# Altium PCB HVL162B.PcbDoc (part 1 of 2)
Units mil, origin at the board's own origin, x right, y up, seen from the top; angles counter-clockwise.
Board outline 4000 x 2700 mil, 2 copper layers (Top Layer, Bottom Layer), stack 62 mil thick; 115 components, 45 nets, 233 pads, 126 vias.
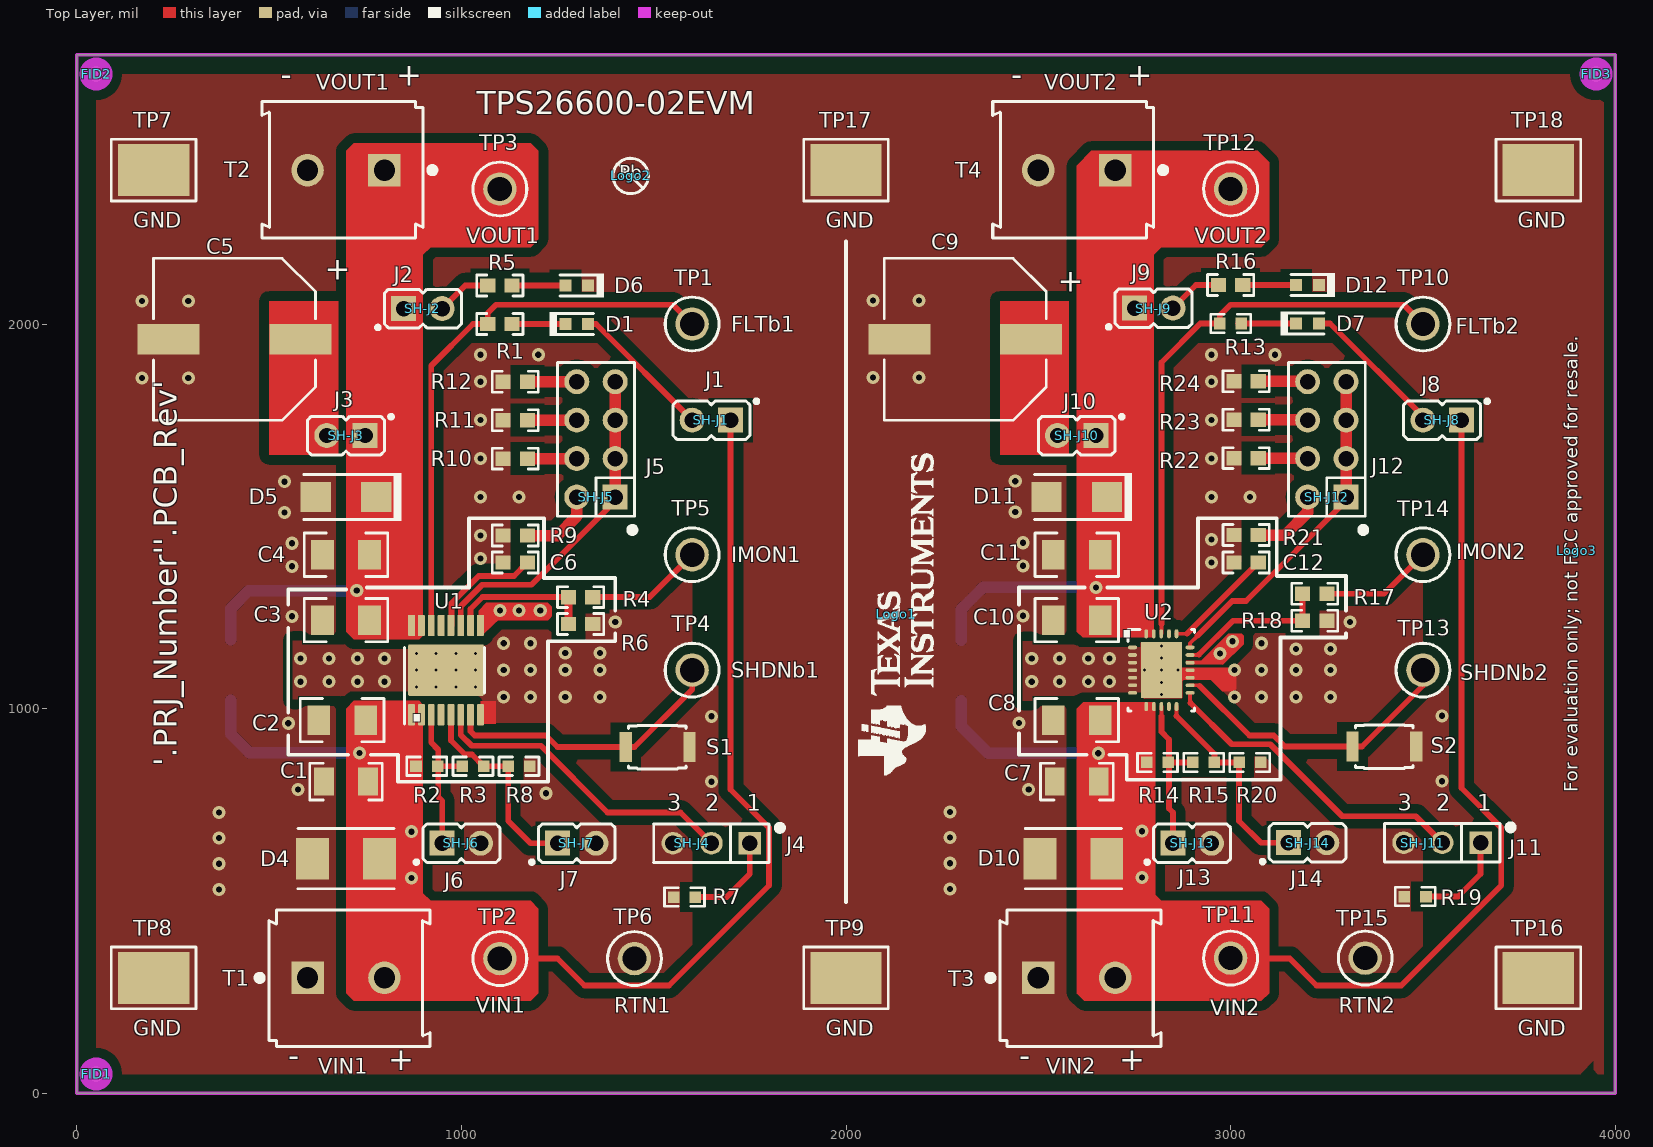
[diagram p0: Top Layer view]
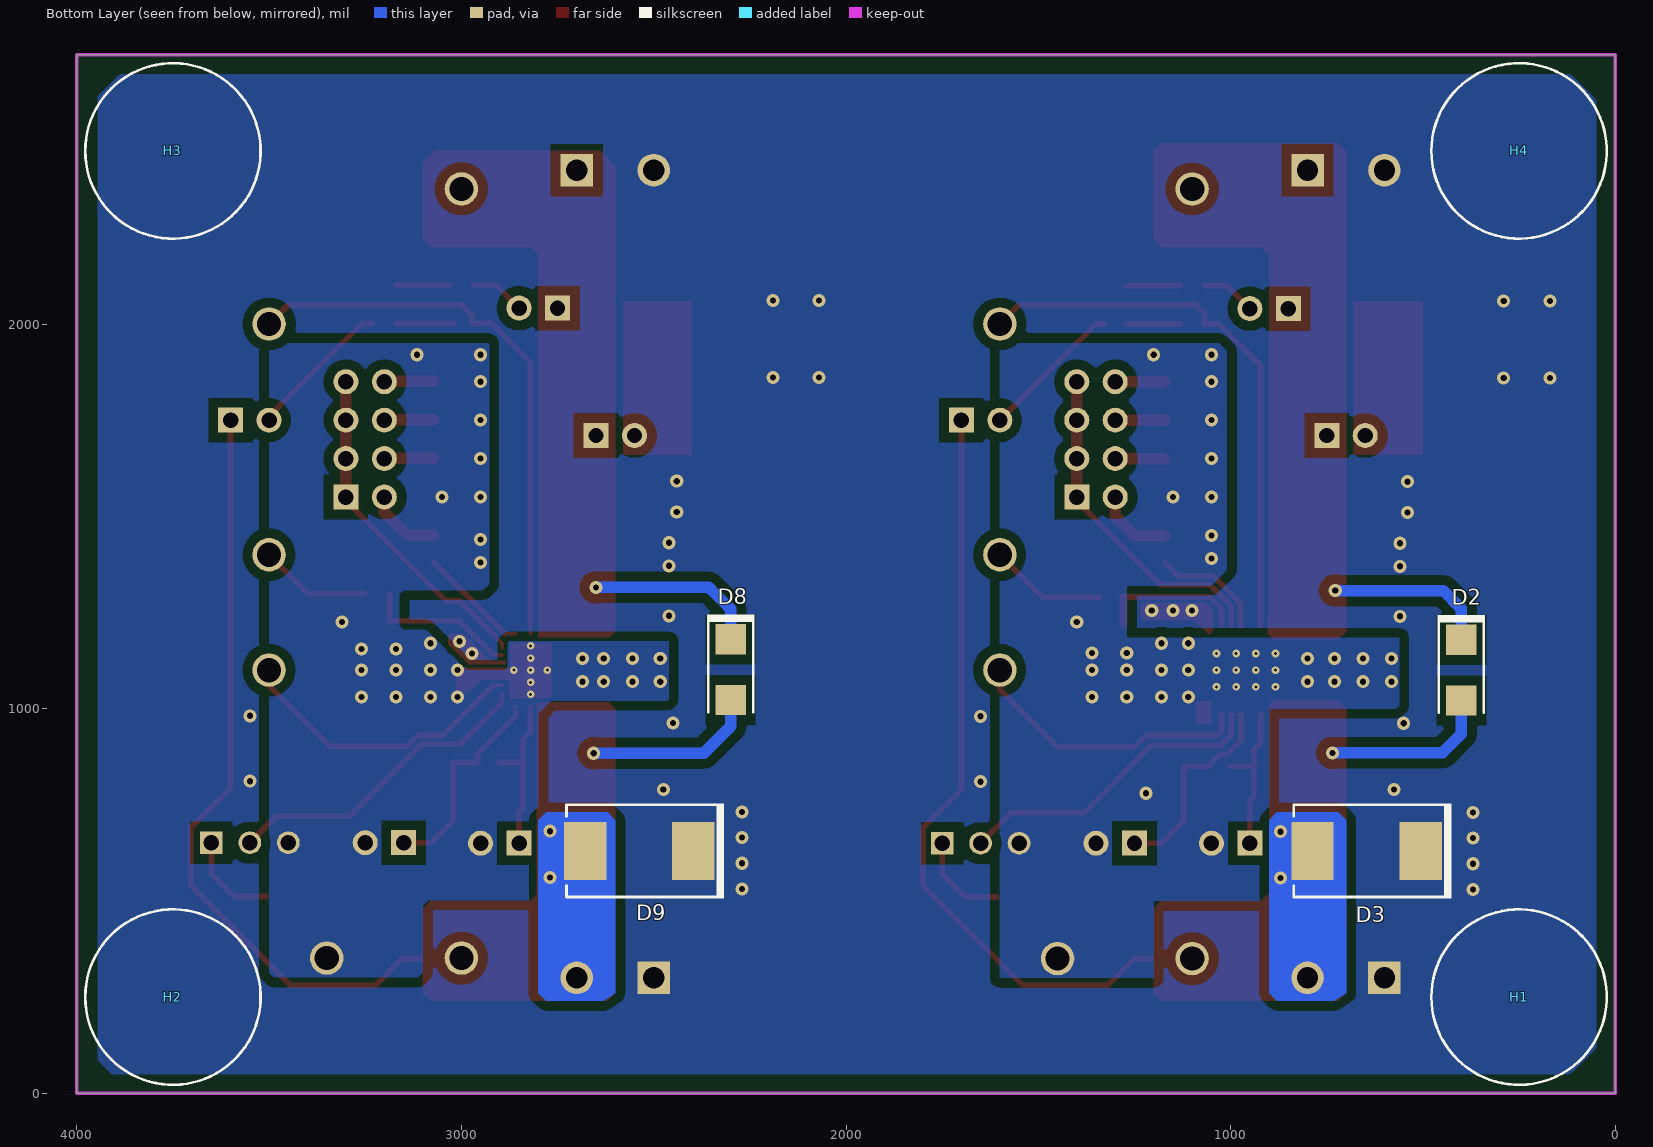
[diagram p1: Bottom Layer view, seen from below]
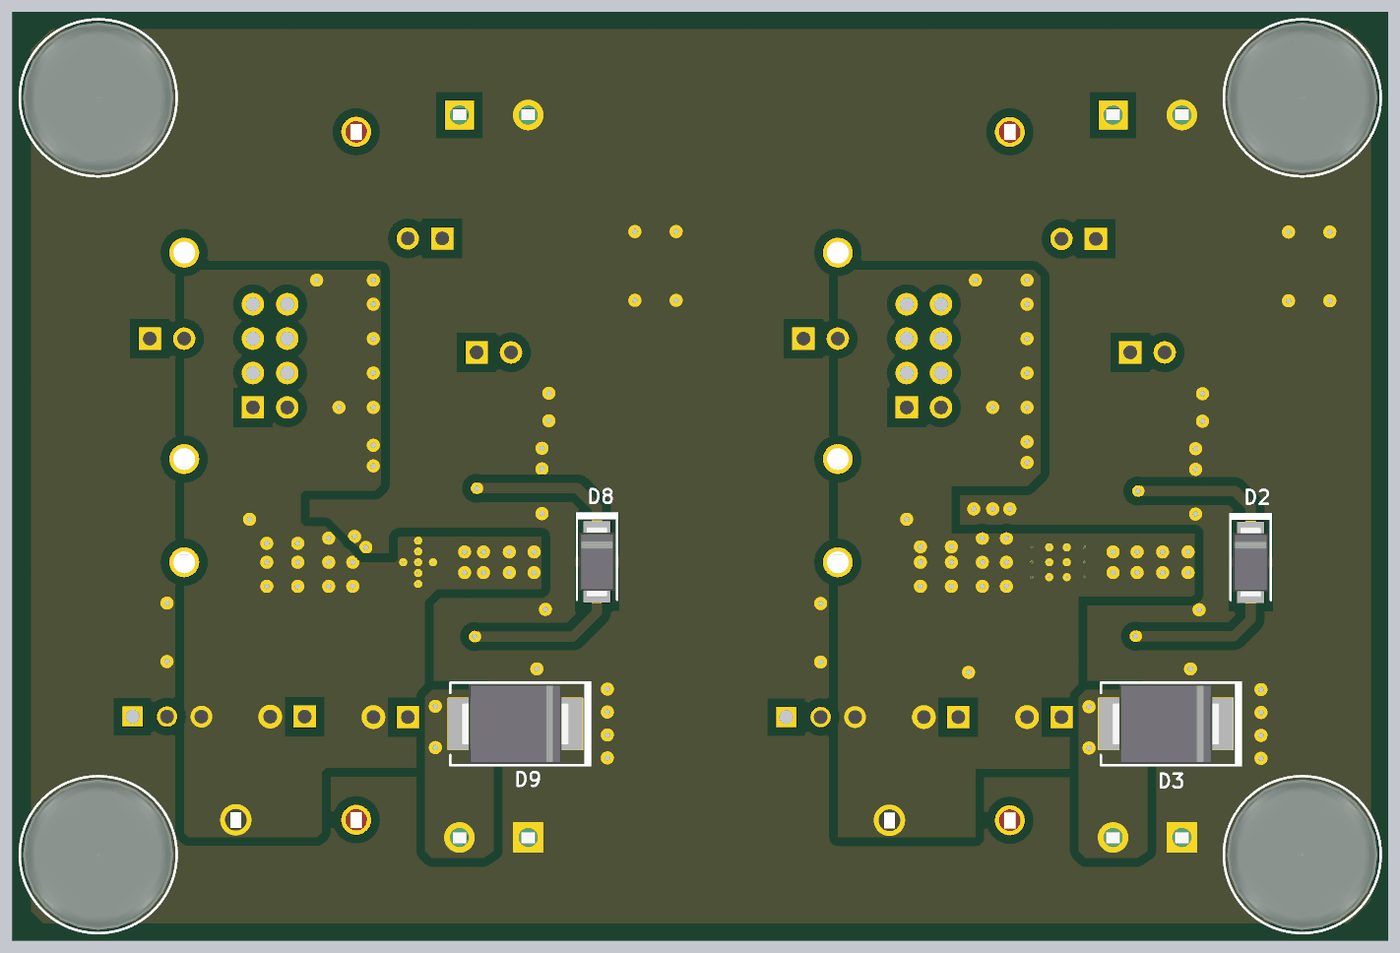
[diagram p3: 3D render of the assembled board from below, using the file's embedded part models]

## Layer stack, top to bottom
Top Solder: solder mask 0.4, Solder Resist, Dk 3.5
Top Layer: signal copper 1.4
Dielectric1: core 59.2, FR-4 High Tg, Dk 4.8
Bottom Layer: signal copper 1.4
Bottom Solder: solder mask 0.4, Solder Resist, Dk 3.5

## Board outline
0,0 0,2700 4000,2700 4000,0

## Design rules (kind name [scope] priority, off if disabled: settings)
AcuteAngle [All] p1: minimum=4.50000000000000E+0001 checktracksonly=FALSE
AssemblyTestPointUsage [All] p1: valid=2
BoardOutlineClearance BoardOutlineClearance_MountingHoles [OnCopper and InComponentClass('Mounting Holes')] p1: gap=40 ignorepadtopadclearanceinfootprint=FALSE
BoardOutlineClearance BoardOutlineClearance_Poly [OnCopper and IsPoly] p2: gap=25 ignorepadtopadclearanceinfootprint=FALSE
BoardOutlineClearance [OnCopper and Not InComponentClass('Logo') and not InComponentClass('FiducialMark') and not InRegion(1000,500,4000,800) and not InPoly] p3: gap=75 ignorepadtopadclearanceinfootprint=FALSE
Clearance Clearance_Keepouts [((IsTrack Or IsArc) And Not InPoly) And IsFree and IsKeepOut vs ((IsTrack Or IsArc) And Not InPoly) And IsFree and IsKeepOut] p1: gap=0 ignorepadtopadclearanceinfootprint=FALSE
Clearance Clearance_Poly [InPolygon] p2: gap=25 ignorepadtopadclearanceinfootprint=FALSE except(0: Arc-Hole Track-Hole SMDPad-Hole THPad-Hole Via-Hole Fill-Hole Poly-Hole Region-Hole Text-Hole)
Clearance Clearance_FiducialMark [IsKeepOut and InComponentClass('FiducialMark') vs IsPad and InComponentClass('FiducialMark')] p3: gap=0 ignorepadtopadclearanceinfootprint=FALSE
Clearance [All] p4: gap=7.87 ignorepadtopadclearanceinfootprint=FALSE except(0: Arc-Hole Track-Hole SMDPad-Hole THPad-Hole Via-Hole Fill-Hole Poly-Hole Region-Hole Text-Hole)
ComponentClearance ComponentClearance_MountingHoles_FiducialMarks [InComponentClass('Mounting Holes') vs InComponentClass('FiducialMark')] p1: gap=50 collisioncheckmode=3 verticalgap=10 showdistances=FALSE
ComponentClearance ComponentClearance_Shunt [InComponentClass('Header') vs InComponentClass('Shunt')] p2: gap=0 collisioncheckmode=3 verticalgap=0 showdistances=FALSE
ComponentClearance ComponentClearance_Logo [InComponentClass('Logo')] p3: gap=50 collisioncheckmode=3 verticalgap=10 showdistances=FALSE
ComponentClearance ComponentClearance_ScrewToNut [(HasFootprint('NY PMS 440 0025 PH')) vs (HasFootprint('Keystone_1902C'))] p4: gap=5 collisioncheckmode=3 verticalgap=10 showdistances=FALSE
ComponentClearance ComponentClearance_MountingHoles [InComponentClass('Mounting Holes')] p5: gap=250 collisioncheckmode=3 verticalgap=100000 showdistances=FALSE
ComponentClearance ComponentClearance_SmallPassives [HasFootprint('0201*') or HasFootprint('0402*') or HasFootprint('0508') or HasFootprint('0603*') or HasFootprint('0612') or HasFootprint('0805*') or HasFootprint('0815*') or HasFootprint('0830*') or HasFootprint('1206*') or HasFootprint('1210*') or HasFootprint('1808*') or HasFootprint('1812*') or HasFootprint('1825*') or HasFootprint('2010*') or HasFootprint('2220*') or HasFootprint('2225*') or HasFootprint('2512*') or HasFootprint('2728*') or HasFootprint('3518*') vs HasFootprint('0201*') or HasFootprint('0402*') or HasFootprint('0508') or HasFootprint('0603*') or HasFootprint('0612') or HasFootprint('0805*') or HasFootprint('0815*') or HasFootprint('0830*') or HasFootprint('1206*') or HasFootprint('1210*') or HasFootprint('1808*') or HasFootprint('1812*') or HasFootprint('1825*') or HasFootprint('2010*') or HasFootprint('2220*') or HasFootprint('2225*') or HasFootprint('2512*') or HasFootprint('2728*') or HasFootprint('3518*')] p6: gap=14.96 collisioncheckmode=3 verticalgap=10 showdistances=FALSE
ComponentClearance ComponentClearance_THtoSMT [IsThruComponent vs IsSMTComponent] p7: gap=40 collisioncheckmode=3 verticalgap=30 showdistances=FALSE
ComponentClearance ComponentClearance_THtoTH [IsThruComponent vs IsThruComponent] p8: gap=30 collisioncheckmode=3 verticalgap=30 showdistances=FALSE
ComponentClearance [All] p9: gap=30 collisioncheckmode=3 verticalgap=10 showdistances=FALSE
DiffPairsRouting [All] p1: maxlimit=100 minlimit=10 mostfreqgap=10 toplayer_minwidth=15 toplayer_maxwidth=15 toplayer_prefwidth=15 bottomlayer_minwidth=15 bottomlayer_maxwidth=15 bottomlayer_prefwidth=15 maxuncoupledlength=1000
FabricationTestPointUsage TestPointUsage [All] p1: valid=2 allowmultiple=FALSE
FabricationTestpoint Testpoint [All] p1: side=3 testpointundercomponent=TRUE minsize=40 maxsize=100 preferedsize=60 minholesize=0 maxholesize=40 preferedholesize=32 testpointgrid=1 allowsidetop=TRUE allowsidebottom=TRUE usegrid=TRUE gridtolerance=0.01
FanoutControl Fanout_LCC [IsLCC] p1: bgadir=Out bgaviamode=Centered fanoutstyle=Auto fanoutdirection=Alternating viagrid=1 // Fanout_LCC (Default Rule)
FanoutControl Fanout_BGA [IsBGA] p2: bgadir=Out bgaviamode=Centered fanoutstyle=Auto fanoutdirection=Alternating viagrid=1 // Fanout_BGA (Default Rule)
FanoutControl Fanout_Default [All] p4: bgadir=Out bgaviamode=Centered fanoutstyle=Auto fanoutdirection=Alternating viagrid=1 // Fanout_Default (Default Rule)
FanoutControl Fanout_Small [(CompPinCount < 5)] p5: bgadir=Out bgaviamode=Centered fanoutstyle=Auto fanoutdirection=OutThenIn viagrid=1 // Fanout_Small (Default Rule)
HoleSize [All] p1: absolutevalues=TRUE maxlimit=251 minlimit=7.87 maxpercent=80.000 minpercent=20.000
MinimumAnnularRing MinimumAnnularRing_ThermalPadVias [IsVia and InAnyComponent] p1: minimumring=5.91
MinimumAnnularRing [All] p2: minimumring=8
MinimumSolderMaskSliver MinimumSolderMaskSliver_Logo [InComponentClass('Logo') vs InComponentClass('Logo')] p1: minsoldermaskwidth=0.7
MinimumSolderMaskSliver [All] p2: minsoldermaskwidth=3.94
PlaneConnect [All] p1: planeconnectstyle=Relief reliefexpansion=10 reliefentries=4 reliefconductorwidth=10 reliefairgap=10
PolygonConnect [All] p1: connectstyle=Direct reliefconductorwidth=10 reliefentries=4 polygonreliefangle="90 Angle" airgapwidth=10
RoutingVias ThermalPadVias [IsVia and InAnyComponent] p1: holewidth=7.87 width=19.68 viastyle="Through Hole" minholewidth=7.87 minwidth=19.68 maxholewidth=12.99 maxwidth=23.62
RoutingVias [All] p2: holewidth=16 width=34 viastyle="Through Hole" minholewidth=7.87 minwidth=26 maxholewidth=40 maxwidth=65
SilkToBoardRegionClearance [Not ((IsComment or IsDesignator) And (Hide <> 'False')) and not InRegion(1000,500,4000,800)] p1:
SilkToSilkClearance SilkToSilkClearance_Pb-FreeLogo [(HasFootprint('Pb-Free_Overlay_Medium') OR HasFootprint('Pb-Free_Overlay_Small')) vs (HasFootprint('Pb-Free_Overlay_Medium') OR HasFootprint('Pb-Free_Overlay_Small'))] p1: silktosilkclearance=0
SilkToSilkClearance [All] p2: silktosilkclearance=3
SilkToSolderMaskClearance SilkToComponentPadClearance [IsPad and InAnycomponent] p1: minsilkscreentomaskgap=5 clearancetoexposedcopper=TRUE
SilkToSolderMaskClearance "Silk to Solder Mask Opening" [All] p2: minsilkscreentomaskgap=4 clearancetoexposedcopper=FALSE
SolderMaskExpansion [All] p1: expansion=1.97
Width [All] p1: maxlimit=100 minlimit=6 preferedwidth=10 checkconnectedcopper=TRUE
15 further rules are at their usual default settings.

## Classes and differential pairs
component class AssemblyNote: ZZ2 ZZ3 ZZ4
component class FiducialMark: FID1 FID2 FID3
component class HVL162B_Hardware: FID1 FID2 FID3 H1 H2 H3 H4 Logo1 Logo2 Logo3 SH-J1 SH-J2 SH-J3 SH-J4 SH-J5 SH-J6 SH-J7 SH-J8 SH-J9 SH-J10 SH-J11 SH-J12 SH-J13 SH-J14 ZZ2 ZZ3 ZZ4
component class Logo: Logo1
component class HVL162B: C1 C2 C3 C4 C5 C6 C7 C8 C9 C10 C11 C12 D1 D2 D3 D4 D5 D6 D7 D8 D9 D10 D11 D12 J1 J2 J3 J4 J5 J6 J7 J8 J9 J10 J11 J12 J13 J14 R1 R2 R3 R4 R5 R6 R7 R8 R9 R10 R11 R12 R13 R14 R15 R16 R17 R18 R19 R20 R21 R22 R23 R24 S1 S2 T1 T2 T3 T4 TP1 TP2 TP3 TP4 TP5 TP6 TP7 TP8 TP9 TP10 TP11 TP12 TP13 TP14 TP15 TP16 TP17 TP18 U1 U2
component class Header: J1 J2 J3 J4 J5 J6 J7 J8 J9 J10 J11 J12 J13 J14
component class Shunt: SH-J1 SH-J2 SH-J3 SH-J4 SH-J5 SH-J6 SH-J7 SH-J8 SH-J9 SH-J10 SH-J11 SH-J12 SH-J13 SH-J14

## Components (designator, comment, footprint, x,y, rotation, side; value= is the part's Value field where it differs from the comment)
C1 "GRM319R72A104KA01D" 1206 700,810 r180 top value=0.1uF
C2 "GRM31CR72A105KA01L" 1206_180M 690,970 r0 top value=1uF
C3 "GRM31CR72A105KA01L" 1206_180M 700,1230 r180 top value=1uF
C4 "GRM31CR72A105KA01L" 1206_180M 700,1400 r180 top value=1uF
C5 "EEETG1J470P" SM_RADIAL_G 410,1960 r180 top value=47uF
C6 "GRM188R71C223KA01D" 0603 1140,1380 r180 top value=0.022uF
C7 "GRM319R72A104KA01D" 1206 2600,810 r180 top value=0.1uF
C8 "GRM31CR72A105KA01L" 1206_180M 2600,970 r0 top value=1uF
C9 "EEETG1J470P" SM_RADIAL_G 2310,1960 r180 top value=47uF
C10 "GRM31CR72A105KA01L" 1206_180M 2600,1230 r180 top value=1uF
C11 "GRM31CR72A105KA01L" 1206_180M 2600,1400 r180 top value=1uF
C12 "GRM188R71C223KA01D" 0603 3040.33,1380 r180 top value=0.022uF
D1 "LTST-C190CKT" LED_LTST-C190_Red 1300,2000 r180 top value=Red
D2 "SMAJ51CA" SMA 400,1100 r270 bottom value=51V
D3 "" SMC 646.52,630 r0 bottom value=36V
D4 "SMBJ51CA" SMB-Bi 700,610 r0 top value=51V
D5 "B260A-13-F" SMA 700,1550 r180 top value=60V
D6 "LTST-C190GKT" LED_LTST-C190 1300,2100 r0 top value=Green
D7 "LTST-C190CKT" LED_LTST-C190_Red 3200,2001.3 r180 top value=Red
D8 "SMAJ51CA" SMA 2300,1101.3 r270 bottom value=51V
D9 "" SMC 2537.69,630 r0 bottom value=36V
D10 "SMBJ51CA" SMB-Bi 2591.17,610 r0 top value=51V
D11 "B260A-13-F" SMA 2600,1550 r180 top value=60V
D12 "LTST-C190GKT" LED_LTST-C190 3200,2101.3 r0 top value=Green
FID1 "Fiducial" Fiducial10-20 50,50 r0 top
FID2 "Fiducial" Fiducial10-20 50,2650 r0 top
FID3 "Fiducial" Fiducial10-20 3950,2650 r0 top
H1 "" Bumpon_SJ5003Transparent 250,250 r180 bottom
H2 "" Bumpon_SJ5003Transparent 3750,250 r180 bottom
H3 "" Bumpon_SJ5003Transparent 3750,2450 r180 bottom
H4 "" Bumpon_SJ5003Transparent 250,2450 r180 bottom
J1 "PBC02SAAN" Sullins_PBC02SAAN 1650,1750 r270 top
J2 "PBC02SAAN" Sullins_PBC02SAAN 900,2040 r90 top
J3 "PBC02SAAN" Sullins_PBC02SAAN 700,1710 r270 top
J4 "" CONN_PEC03SAAN 1650,650 r180 top
J5 "PEC04DAAN" CONN_PEC04DAAN 1350,1700 r90 top
J6 "PBC02SAAN" Sullins_PBC02SAAN 1000,650 r90 top
J7 "PBC02SAAN" Sullins_PBC02SAAN 1300,650 r90 top
J8 "PBC02SAAN" Sullins_PBC02SAAN 3550,1750 r270 top
J9 "PBC02SAAN" Sullins_PBC02SAAN 2800,2041.3 r90 top
J10 "PBC02SAAN" Sullins_PBC02SAAN 2600,1710 r270 top
J11 "" CONN_PEC03SAAN 3550,651.3 r180 top
J12 "PEC04DAAN" CONN_PEC04DAAN 3250.33,1700 r90 top
J13 "PBC02SAAN" Sullins_PBC02SAAN 2900,650 r90 top
J14 "PBC02SAAN" Sullins_PBC02SAAN 3200,651.3 r90 top
Logo1 "Texas Instruments" TI_Stacked_Overlay_Small 2130,1245 r90 top
Logo2 "Pb-Free Symbol" Pb-Free_Overlay_Small 1440,2385 r0 top
Logo3 "FCC disclaimer" FCC_disclaimer 3900,1410 r90 top
R1 "CRCW060324K3FKEA" 0603 1100,2000 r0 top value=24.3k
R2 "CRCW0603887KFKEA" 0603_HV 910,850 r180 top value=887k
R3 "CRCW060390K9FKEA" 0603_HV 1030,850 r180 top value=90.9k
R4 "CRCW0603100KFKEA" 0603 1310,1290 r180 top value=100k
R5 "CRCW060324K3FKEA" 0603 1100,2100 r180 top value=24.3k
R6 "CRCW060320K0FKEA" 0603 1310,1220 r180 top value=20.0k
R7 "CRCW0603402KFKEA" 0603_HV 1580,510 r0 top value=402k
R8 "CRCW060330K1FKEA" 0603_HV 1150,850 r180 top value=30.1k
R9 "CRCW06035K36FKEA" 0603 1140,1450 r0 top value=5.36k
R10 "CRCW06038K06FKEA" 0603 1140,1650 r0 top value=8.06k
R11 "CRCW060312K1FKEA" 0603 1140,1750 r0 top value=12.1k
R12 "CRCW060360K4FKEA" 0603 1140,1850 r0 top value=60.4k
R13 "CRCW060324K3FKEA" 0603_HV 3000,2001.3 r0 top value=24.3k
R14 "CRCW0603887KFKEA" 0603_HV 2810,860 r180 top value=887k
R15 "CRCW060390K9FKEA" 0603_HV 2930,860 r180 top value=90.9k
R16 "CRCW060324K3FKEA" 0603 3000,2101.3 r180 top value=24.3k
R17 "CRCW0603100KFKEA" 0603 3218.7,1298.7 r180 top value=100k
R18 "CRCW060320K0FKEA" 0603 3218.7,1228.7 r180 top value=20.0k
R19 "CRCW0603402KFKEA" 0603_HV 3480,511.3 r0 top value=402k
R20 "CRCW060330K1FKEA" 0603_HV 3050,860 r180 top value=30.1k
R21 "CRCW06035K36FKEA" 0603 3040.33,1451.3 r0 top value=5.36k
R22 "CRCW06038K06FKEA" 0603 3040.33,1651.3 r0 top value=8.06k
R23 "CRCW060312K1FKEA" 0603 3040.33,1751.3 r0 top value=12.1k
R24 "CRCW060360K4FKEA" 0603 3040.33,1851.3 r0 top value=60.4k
S1 "RES-2" SW_SKRKAEE010 1510,900 r180 top
S2 "RES-2" SW_SKRKAEE010 3400,901.3 r180 top
SH-J1 "SPC02SYAN" SPC02SYAN 1650,1750 r180 top value=1x2
SH-J2 "SPC02SYAN" SPC02SYAN 900,2040 r180 top value=1x2
SH-J3 "SPC02SYAN" SPC02SYAN 700,1710 r180 top value=1x2
SH-J4 "SPC02SYAN" SPC02SYAN 1600,650 r180 top value=1x2
SH-J5 "SPC02SYAN" SPC02SYAN 1350,1550 r180 top value=1x2
SH-J6 "SPC02SYAN" SPC02SYAN 1000,650 r180 top value=1x2
SH-J7 "SPC02SYAN" SPC02SYAN 1300,650 r180 top value=1x2
SH-J8 "SPC02SYAN" SPC02SYAN 3550,1750 r180 top value=1x2
SH-J9 "SPC02SYAN" SPC02SYAN 2800,2040 r180 top value=1x2
SH-J10 "SPC02SYAN" SPC02SYAN 2600,1710 r180 top value=1x2
SH-J11 "SPC02SYAN" SPC02SYAN 3500,650 r180 top value=1x2
SH-J12 "SPC02SYAN" SPC02SYAN 3250,1550 r180 top value=1x2
SH-J13 "SPC02SYAN" SPC02SYAN 2900,650 r180 top value=1x2
SH-J14 "SPC02SYAN" SPC02SYAN 3200,650 r180 top value=1x2
T1 "VIN1" TEC_282841-2 700,300 r0 top
T2 "VOUT1" TEC_282841-2 700,2400 r180 top
T3 "VIN2" TEC_282841-2 2600,300 r0 top
T4 "VOUT2" TEC_282841-2 2600,2400 r180 top
TP1 "FLTb1" Keystone5012 1600,2000 r0 top value=White
TP2 "VIN1" Keystone5010 1100,350 r0 top value=Red
TP3 "VOUT1" Keystone5010 1100,2350.98 r0 top value=Red
TP4 "SHDNb1" Keystone5012 1600,1100 r0 top value=White
TP5 "IMON1" Keystone5012 1600,1400 r0 top value=White
TP6 "RTN1" Keystone5011 1450,350 r0 top value=Black
TP7 "GND" Testpoint_Keystone_Compact 200,2400 r0 top value=SMT
TP8 "GND" Testpoint_Keystone_Compact 200,300 r0 top value=SMT
TP9 "GND" Testpoint_Keystone_Compact 2000,300 r0 top value=SMT
TP10 "FLTb2" Keystone5012 3500,2000 r0 top value=White
TP11 "VIN2" Keystone5010 3000,351.3 r0 top value=Red
TP12 "VOUT2" Keystone5010 3000,2351.3 r0 top value=Red
TP13 "SHDNb2" Keystone5012 3500,1100 r0 top value=White
TP14 "IMON2" Keystone5012 3500,1400 r0 top value=White
TP15 "RTN2" Keystone5011 3350,351.3 r0 top value=Black
TP16 "GND" Testpoint_Keystone_Compact 3800,300 r0 top value=SMT
TP17 "GND" Testpoint_Keystone_Compact 2000,2400 r0 top value=SMT
TP18 "GND" Testpoint_Keystone_Compact 3800,2400 r0 top value=SMT
U1 "CMP-0074228-2" PWP0016H_N 960,1100 r90 top
U2 "TPS26600RHF" RHF0024A 2820,1100 r0 top
ZZ2 "These assemblies are ESD sensitive, ESD precautions shall be observed." AssemblyNote 145,3280 r0 top
ZZ3 "These assemblies must be clean and free from flux and all contaminants. Use of no clean flux is not acceptable." AssemblyNote 145,3060 r0 top
ZZ4 "These assemblies must comply with workmanship standards IPC-A-610 Class 2, unless otherwise specified." AssemblyNote 145,3180 r0 top

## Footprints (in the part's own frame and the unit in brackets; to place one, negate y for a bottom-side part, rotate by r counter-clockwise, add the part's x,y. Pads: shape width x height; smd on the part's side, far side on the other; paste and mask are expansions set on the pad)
0603 [mm] "0603 from SM-752 data"
  rect 1x0.95 smd: 1(-0.8,0) 2(0.8,0)
  silkscreen extent -1.52,-0.69 1.52,0.69, body extent -0.87,-0.47 0.87,0.47, height 1
0603_HV [mil] "Ernesto recommended land pattern.  26 mil between pads."
  rect 30x30 smd: 1(-28,0) 2(28,0)
  silkscreen extent -52,-24 52,24, body extent -34,-19 34,19, height 39
1206 [mm] "1206 from SM-752 data"
  rect 1.3x1.85 smd: 1(-1.45,0) 2(1.45,0)
  silkscreen extent -2.4,-1.21 2.4,1.21, body extent -1.7,-0.9 1.7,0.9, height 1.35
1206_180M [mm] "1206_180"
  rect 1.5x1.95 smd: 1(-1.55,0) 2(1.55,0)
  silkscreen extent -2.76,-1.44 2.76,1.44, body extent -1.75,-0.95 1.75,0.95, height 1.8
AssemblyNote [mil] "Assembly Note"
Bumpon_SJ5003Transparent [mil] "3M Hemispherical Bumpon transparent"
  round 1 on Mech4: 0(0,0)
  silkscreen extent -228,-228 228,228, body extent -219,-219 219,219, height 197
CONN_PEC03SAAN [mm] "SULLINS"
  rect 1.5x1.5 hole 1.016: 1(-2.54,0)
  round 1.5 hole 1.016: 2(0,0) 3(2.54,0)
  silkscreen extent -4.72,-1.27 3.81,1.27, body extent -3.84,-1.3 3.84,1.3, height 8.38
CONN_PEC04DAAN [mm] "SULLINS"
  rect 1.65x1.65 hole 1.016 mask+0: 1(-3.81,-1.27)
  round 1.65 hole 1.016 mask+0: 2(-3.81,1.27) 3(-1.27,-1.27) 4(-1.27,1.27) 5(1.27,-1.27) 6(1.27,1.27) 7(3.81,-1.27) 8(3.81,1.27)
  silkscreen extent -6.18,-2.6 5.08,2.54, body extent -5.08,-2.54 5.08,2.54, height 8.38
FCC_disclaimer [mil]
Fiducial10-20 [mm]
  round 1 smd mask+0.5: 1(0,0)
  Top Layer keep-out circle w1.178: c0,0 r0.5
Keystone5010 [mil] "Keystone Multipurpose loops"
  round 87 hole 63: 1(0,0)
  silkscreen extent -70,-70 70,70, body extent -63,-63 63,62, height 319
Keystone5011 [mil] "Keystone Multipurpose loops"
  round 87 hole 63: 1(0,0)
  silkscreen extent -70,-70 70,70, body extent -63,-63 63,62, height 319
Keystone5012 [mil] "Keystone Multipurpose loops"
  round 87 hole 63: 1(0,0)
  silkscreen extent -70,-70 70,70, body extent -63,-63 63,62, height 319
LED_LTST-C190 [mm] "Lite-On"
  rect 0.8x0.8 smd: 1(-0.75,0) 2(0.75,0)
  silkscreen extent -1.1,-0.8 1.8,0.8, body extent -0.85,-0.45 0.85,0.45, height 0.9
LED_LTST-C190_Red [mm] "Lite-On"
  rect 0.8x0.8 smd: 1(-0.75,0) 2(0.75,0)
  silkscreen extent -1.1,-0.8 1.8,0.8, body extent -0.85,-0.45 0.85,0.45, height 0.9
Pb-Free_Overlay_Small [mil]
  silkscreen extent -46,-46 46,46
PWP0016H_N [mm] "TSOP, 16-Leads, Body 5x4.4mm, Pitch 0.65mm, Thermal Pad 2.48x3.37 mm, IPC Medium Density"
  rrect22% 1.4x0.45 smd: 1(-2.95,2.275) 2(-2.95,1.625) 3(-2.95,0.975) 4(-2.95,0.325) 5(-2.95,-0.325) 6(-2.95,-0.975) 7(-2.95,-1.625) 8(-2.95,-2.275) 9(2.95,-2.275) 10(2.95,-1.625) 11(2.95,-0.975) 12(2.95,-0.325) 13(2.95,0.325) 14(2.95,0.975) 15(2.95,1.625) 16(2.95,2.275)
  rrect6% 3.4x5 smd paste-2 mask-2: 17(0,0)
  rrect4% 2.66x2.46 on Top Paste: 17(0,0)
  rrect4% 2.66x2.46 on Top Solder: 17(0,0)
  silkscreen extent -3.55,-2.55 1.5,2.75, body extent -3.2,-2.5 3.2,2.5, height 1.13
RHF0024A [mm] "TI"
  oval 0.6x0.24 smd: 1(-1.9,1.5) 2(-1.9,1) 3(-1.9,0.5) 4(-1.9,0) 5(-1.9,-0.5) 6(-1.9,-1) 7(-1.9,-1.5) 13(1.9,-1.5) 14(1.9,-1) 15(1.9,-0.5) 16(1.9,0) 17(1.9,0.5) 18(1.9,1) 19(1.9,1.5)
  oval 0.24x0.6 smd: 8(-1,-2.4) 9(-0.5,-2.4) 10(0,-2.4) 11(0.5,-2.4) 12(1,-2.4) 20(1,2.4) 21(0.5,2.4) 22(0,2.4) 23(-0.5,2.4) 24(-1,2.4)
  rect 2.7x3.7 smd paste-1.5: 25(0,0)
  silkscreen extent -2.2,-2.7 2.2,2.7, body extent -2.07,-2.57 2.07,2.57, height 1.01
SM_RADIAL_G [mm] "10 x 10.2mm:  Panasonic G"
  rect 4.1x2 smd: 1(-4.35,0) 2(4.35,0)
  silkscreen extent -5.35,-5.35 5.35,5.35, body extent -5.25,-5.25 5.25,5.25, height 10.5
SMA [mm] "Molded Diode, 2-Leads, Body 4.3x2.6mm, IPC Medium Density, based on OnSemi component dimensions and land pattern"
  rect 2x2 smd: 1(-2,0) 2(2,0)
  silkscreen extent -3.66,-1.57 2.79,1.57, body extent -2.6,-1.3 2.6,1.3, height 2.42
SMB-Bi [mil] "Molded Diode, 2-Leads, Body 5.4x3.6mm, IPC Medium Density, based on OnSemi component dimensions"
  rect 85x107.99 smd: 1(-87.01,0) 2(87.01,0)
  silkscreen extent -125,-79 125,79, body extent -104,-73 104,73, height 89
SMC [mil] "Molded Diode, 2-Leads, Body 6.9x5.8mm, IPC Medium Density, based on OnSemi component dimensions and land patterns"
  rect 110x150 smd: 1(-140.49,0) 2(140.49,0)
  silkscreen extent -221,-124 189,124, body extent -156,-116 156,116, height 91
SPC02SYAN [mil] "SULLINS"
  round 1 on Mech3: 0(0,0)
  body extent -98,-47 99,47, height 366
Sullins_PBC02SAAN [mm] "Sullins 100mil, 1x2, 230 mil above insulator"
  rect 1.65x1.65 hole 1.016: 1(0,1.27)
  round 1.65 hole 1.016: 2(0,-1.27)
  silkscreen extent -1.37,-2.54 1.27,3.1, body extent -1.27,-2.54 1.27,2.54, height 8.38
SW_SKRKAEE010 [mm] "Alps recommended land pattern"
  rect 0.8x2 smd: 1(-2.1,0) 2(2.1,0)
  silkscreen extent -1.9,-1.44 1.92,1.44, body extent -2.4,-1.45 2.4,1.45, height 1.96
TEC_282841-2 [mm] "TE Connectivity"
  rect 2.15x2.15 hole 1.4: 1(-2.54,0)
  round 2.15 hole 1.4: 2(2.54,0)
  silkscreen extent -5.9,-4.52 5.55,4.47, body extent -5.08,-4.52 5.58,4.48, height 15.2
Testpoint_Keystone_Compact [mil] "Compact SMT test point"
  rect 185x135 smd: 1(0,0)
  silkscreen extent -110,-80 110,80, body extent -75,-56 75,56, height 91
TI_Stacked_Overlay_Small [mil]
  silkscreen extent -418,-98 418,98

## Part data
C1 C7: "CAP, CERM, 0.1 µF, 100 V, +/- 10%, X7R, 1206", Cap_Case=1206, Manufacturer=MuRata, Supplier Part Number 1=490-3364-1-ND, TempCo=X7R, Tolerance_%=10, Value1=Unknown, Value2=100V, ValueDisplayed=0.1µF
C2 C3 C4 C8 C10 C11: "CAP, CERM, 1 µF, 100 V, +/- 10%, X7R, 1206", Cap_Case=2220, Manufacturer=MuRata, Supplier Part Number 1=490-3909-1-ND, TempCo=X7R, Tolerance_%=10, Value1=Unknown, Value2=100V, ValueDisplayed=1µF
C5 C9: "CAP, AL, 47 µF, 63 V, +/- 20%,  ohm, SMD", Cap_Case=10x10.2mm, Manufacturer=Panasonic, Supplier Part Number 1=PCE4092CT-ND, Tolerance_%=20, Value1=Unknown, Value2=63V, ValueDisplayed=47µF
C6 C12: "CAP, CERM, 0.022 µF, 16 V, +/- 10%, X7R, 0603", Cap_Case=0603, Manufacturer=MuRata, Supplier Part Number 1=490-1527-1-ND, TempCo=X7R, Tolerance_%=10, Value1=Unknown, Value2=16V, ValueDisplayed=0.022µF
D1 D7: "LED, Red, SMD", Color=red, Manufacturer=Lite-On, Power_TotalModule=0.0625, Supplier Part Number 1=160-1181-1-ND, Value1=0.0625W, Value2=2V
D2 D8: "Diode, TVS, Bi, 51 V, 400 W, SMA", Manufacturer=Littelfuse, Power_W=400, Supplier Part Number 1=SMAJ51CALFDKR-ND, Value1=400W
D3 D9: library part SMCJ33CA, "TVS DIODE 36VWM 58.1VC SMC", Manufacturer=Bourns, PartNumber=SMCJ36CA, Power_W=1500, Supplier Part Number 1=SMCJ36CALFCT-ND, Value1=1500W
D4 D10: "Diode, TVS, Bi, 51 V, 600 W, SMB", Manufacturer=Bourns, Power_W=600, Supplier Part Number 1=SMBJ51CABCT-ND, Value1=600W
D5 D11: "Diode, Schottky, 60 V, 2 A, SMA", Manufacturer="Diodes Inc.", Supplier Part Number 1=B260A-FDICT-ND, Value1=2A, Value2=0.7V
D6 D12: "LED, Green, SMD", Color=green, Manufacturer=Lite-On, Power_TotalModule=0.1, Supplier Part Number 1=160-1183-1-ND, Value1=0.1W, Value2=2.1V
FID1 FID2 FID3: "Fiducial mark.  There is nothing to buy or mount.", Manufacturer=N/A
H1 H2 H3 H4: library part "SJ-5303 (CLEAR)", "Bumpon, Hemisphere, 0.44 X 0.20, Clear", Manufacturer=3M, Supplier Part Number 1=SJ5303-7-ND
J1 J6 J7 J8 J13 J14: "Header, 100mil, 2x1, Gold, TH", Color=Black, Current_A=3, Manufacturer="Sullins Connector Solutions", Supplier Part Number 1=S1011E-02-ND, Voltage_V=1800
J2 J3 J9 J10: "Header, 100mil, 2x1, Gold, TH", Manufacturer="Sullins Connector Solutions", Supplier Part Number 1=S1011E-02-ND
J4 J11: library part PEC03SAAN, "Header, 100mil, 3x1, Tin, TH", Manufacturer="Sullins Connector Solutions", Supplier Part Number 1=S1012E-03-ND
J5 J12: "Header, 100mil, 4x2, Tin, TH", Manufacturer="Sullins Connector Solutions", Supplier Part Number 1=S2012E-04-ND
Logo1: library part TI_Logo, "Texas Instrument Corporate Signature"
Logo2: library part Pb-Free
Logo3: library part FCC_disclaimer, "FCC_disclaimer"
R1 R5 R13 R16: "RES, 24.3 k, 1%, 0.1 W, 0603", Manufacturer=Vishay-Dale, Power_W=0.1, Supplier Part Number 1=541-24.3KHCT-ND, TempCo="100 ppm/C", Tolerance_%=1, Value1=1%, Value2=0.1W, Value_Code=24k3, ValueDisplayed=24.3k
R2 R14: "RES, 887 k, 1%, 0.1 W, 0603", Manufacturer=Vishay-Dale, Power_W=0.1, Supplier Part Number 1=541-887KHCT-ND, TempCo="100 ppm/C", Tolerance_%=1, Value1=1%, Value2=0.1W, Value_Code=887k
R3 R15: "RES, 90.9 k, 1%, 0.1 W, 0603", Manufacturer=Vishay-Dale, Power_W=0.1, Supplier Part Number 1=541-90.9KHCT-ND, TempCo="100 ppm/C", Tolerance_%=1, Value1=1%, Value2=0.1W, Value_Code=90k9, ValueDisplayed=90.9k
R4 R17: "RES, 100 k, 1%, 0.1 W, 0603", Manufacturer=Vishay-Dale, Power_W=0.1, Supplier Part Number 1=541-100KHCT-ND, TempCo="100 ppm/C", Tolerance_%=1, Value1=1%, Value2=0.1W, Value_Code=100k
R6 R18: "RES, 20.0 k, 1%, 0.1 W, 0603", Manufacturer=Vishay-Dale, Power_W=0.1, Supplier Part Number 1=541-20.0KHCT-ND, TempCo="100 ppm/C", Tolerance_%=1, Value1=1%, Value2=0.1W, Value_Code=20k0, ValueDisplayed=20.0k
R7 R19: "RES, 402 k, 1%, 0.1 W, 0603", Manufacturer=Vishay-Dale, Power_W=0.1, Supplier Part Number 1=541-402KHCT-ND, TempCo="100 ppm/C", Tolerance_%=1, Value1=1%, Value2=0.1W, Value_Code=402k
R8 R20: "RES, 30.1 k, 1%, 0.1 W, 0603", Manufacturer=Vishay-Dale, Power_W=0.1, Supplier Part Number 1=541-30.1KHCT-ND, TempCo="100 ppm/C", Tolerance_%=1, Value1=1%, Value2=0.1W, Value_Code=30k1, ValueDisplayed=30.1k
R9 R21: "RES, 5.36 k, 1%, 0.1 W, 0603", Manufacturer=Vishay-Dale, Power_W=0.1, Supplier Part Number 1=541-5.36KHCT-ND, TempCo="100 ppm/C", Tolerance_%=1, Value1=1%, Value2=0.1W, Value_Code=5k36, ValueDisplayed=5.36k
R10 R22: "RES, 8.06 k, 1%, 0.1 W, 0603", Manufacturer=Vishay-Dale, Power_W=0.1, Supplier Part Number 1=541-8.06KHCT-ND, TempCo="100 ppm/C", Tolerance_%=1, Value1=1%, Value2=0.1W, Value_Code=8k06, ValueDisplayed=8.06k
R11 R23: "RES, 12.1 k, 1%, 0.1 W, 0603", Manufacturer=Vishay-Dale, Power_W=0.1, Supplier Part Number 1=541-12.1KHCT-ND, TempCo="100 ppm/C", Tolerance_%=1, Value1=1%, Value2=0.1W, Value_Code=12k1, ValueDisplayed=12.1k
R12 R24: "RES, 60.4 k, 1%, 0.1 W, 0603", Manufacturer=Vishay-Dale, Power_W=0.1, Supplier Part Number 1=541-60.4KHCT-ND, TempCo="100 ppm/C", Tolerance_%=1, Value1=1%, Value2=0.1W, Value_Code=60k4, ValueDisplayed=60.4k
S1 S2: library part SKRKAEE010, "Switch, Push Button, SMD", Alternate Manufacturer=Any, Alternate PartNumber=Equivalent, CurrentRating_mA=50, Manufacturer=Alps, Supplier Part Number 1=688-SKRKAE
SH-J1 SH-J2 SH-J3 SH-J4 SH-J5 SH-J6 SH-J7 SH-J8 SH-J9 SH-J10 SH-J11 SH-J12 SH-J13 SH-J14: "Shunt, 100mil, Flash Gold, Black", Manufacturer="Sullins Connector Solutions", Supplier Part Number 1=S9001-ND
T1 T2 T3 T4: library part 282841-2, "Terminal Block, 2x1, 5.08mm, TH", Manufacturer="TE Connectivity", Supplier Part Number 1=A98342-ND
TP1 TP4 TP5 TP10 TP13 TP14: library part 5012, "Test Point, TH, Multipurpose, White", Alternate Manufacturer=Any, Alternate PartNumber=Equivalent, Manufacturer=Keystone, Supplier Part Number 1=5012K-ND
TP2 TP3 TP11 TP12: library part 5010, "Test Point, Multipurpose, Red, TH", Manufacturer=Keystone, Supplier Part Number 1=5010K-ND
TP6 TP15: library part 5011, "Test Point, Multipurpose, Black, TH", Manufacturer=Keystone, Supplier Part Number 1=36-5011-ND
TP7 TP8 TP9 TP16 TP17 TP18: library part 5016, "Test Point, SMT, Compact", Alternate Manufacturer=Any, Alternate PartNumber=Equivalent, Manufacturer=Keystone, Supplier Part Number 1=5016KCT-ND
U1: "60V 2A Industrial eFuse With Integrated Reverse-Input Polarity Protection, PWP0016H (TSSOP-16)", Alternate Manufacturer="Texas Instruments", Alternate PartNumber=TPS26600PWPT, PartNumber=TPS26600PWPR
U2: library part CMP-0013838-2, "4.5V - 55V, 2A Industrial eFuse with Integrated Reverse Input Polarity Protection, RHF0024A (VQFN-24)", Alternate Manufacturer="Texas Instruments"
ZZ2 ZZ3 ZZ4: library part AssemblyNote, Alternate Manufacturer=-

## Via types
v1: diameter 34, hole 16, Top Layer to Bottom Layer, 107 vias
v2: diameter 19.68, hole 7.87, Top Layer to Bottom Layer, 13 vias
v3: diameter 19.68, hole 7.87, Top Layer to Bottom Layer, tented both sides, 6 vias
